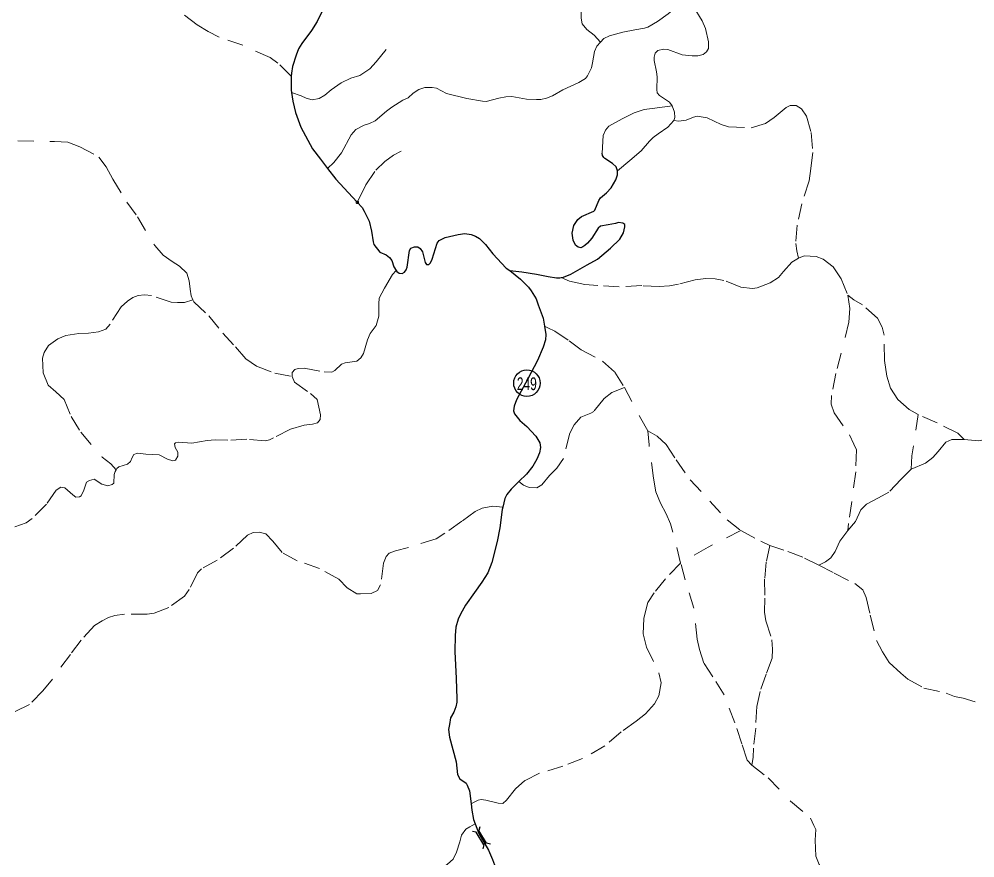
# Model space of a CAD drawing. Extents: x 703.1 to 728.9, y 7316.2 to 7344.3.
# Drawn here: x 719.66 to 725.66, y 7328.43 to 7333.69 of the extents above; entities that cross this region are included whole.
import ezdxf
from ezdxf.enums import TextEntityAlignment as Align

# ---------------------------------------------------------------- set-up
doc = ezdxf.new("R2010")
doc.units = 0
doc.header["$LTSCALE"] = 0.032
doc.header["$PDMODE"] = 32
doc.header["$PDSIZE"] = 0.016
for name, pattern in [('DOTTED', [1.5, 0.3, -1.2]), ('LONG_DASHED', [7.5, 6, -1.5]), ('MEDIUM_DASHED', [4.5, 3, -1.5])]:
    doc.linetypes.add(name, pattern=pattern)
for name, color, linetype, lineweight in [('10', 7, 'Continuous', 25), ('13', 7, 'Continuous', 25), ('4', 7, 'LONG_DASHED', 25), ('5', 7, 'LONG_DASHED', 13), ('6', 7, 'MEDIUM_DASHED', 13), ('7', 7, 'DOTTED', 13)]:
    doc.layers.add(name, color=color, linetype=linetype, lineweight=lineweight)
doc.layers.add('61', color=7, linetype='Continuous')

msp = doc.modelspace()

# ---------------------------------------------------------------- linework, layer by layer
at = {"layer": '10'}
for p, q in [((722.5521, 7328.6293), (722.5462, 7328.6051)), ((722.5942, 7328.526), (722.5462, 7328.6051)), ((722.5771, 7328.5156), (722.5711, 7328.4915)), ((722.6184, 7328.5202), (722.5942, 7328.526))]:
    msp.add_line(p, q, dxfattribs=at)
msp.add_lwpolyline([(722.5771, 7328.5156), (722.5291, 7328.5947), (722.5048, 7328.6006)], dxfattribs=at)
at = {"layer": '13'}
msp.add_circle((722.8471, 7331.4093), 0.083, dxfattribs=at)
at = {"layer": '4'}
for points in [[(721.5179, 7333.9729), (721.5617, 7333.939), (721.5822, 7333.9163), (721.5905, 7333.8858), (721.596, 7333.8481), (721.5803, 7333.7854), (721.562, 7333.7366), (721.5312, 7333.6755), (721.4968, 7333.6184), (721.435, 7333.5369), (721.414, 7333.5036), (721.3993, 7333.4648), (721.3776, 7333.3927), (721.3704, 7333.3522), (721.3692, 7333.3328)], [(721.3692, 7333.3328), (721.368, 7333.3134), (721.368, 7333.2458), (721.3702, 7333.2316)], [(721.3702, 7333.2316), (721.3788, 7333.1759), (721.3959, 7333.1054), (721.43, 7333.0134), (721.4583, 7332.9585), (721.503, 7332.8775), (721.5518, 7332.812), (721.5958, 7332.7533)], [(723.4155, 7332.7388), (723.4057, 7332.7648), (723.3825, 7332.7859), (723.3358, 7332.8165), (723.3281, 7332.8231), (723.3214, 7332.8353), (723.3186, 7332.8497)], [(721.5958, 7332.7533), (721.6496, 7332.6878), (721.7524, 7332.5753), (721.7833, 7332.5426)], [(723.0607, 7332.0703), (723.076, 7332.0733), (723.1214, 7332.0921), (723.2256, 7332.1498), (723.2897, 7332.187), (723.3706, 7332.2541), (723.4299, 7332.3118), (723.4518, 7332.3511), (723.4613, 7332.3883), (723.4602, 7332.4038), (723.4485, 7332.4121), (723.4214, 7332.416), (723.4014, 7332.4105), (723.3571, 7332.401), (723.3088, 7332.3938), (723.2939, 7332.3811), (723.2536, 7332.3179), (723.2259, 7332.2874), (723.2093, 7332.2724), (723.1982, 7332.2635), (723.1849, 7332.258), (723.1677, 7332.2607), (723.1505, 7332.2729), (723.1367, 7332.3046), (723.1306, 7332.3495), (723.1405, 7332.3961), (723.1655, 7332.4349), (723.189, 7332.4543), (723.2661, 7332.4864), (723.2722, 7332.4931), (723.2982, 7332.5546), (723.3082, 7332.5696), (723.3453, 7332.6023), (723.3756, 7332.634), (723.4049, 7332.6839), (723.4155, 7332.7138), (723.4155, 7332.7388)], [(721.7833, 7332.5426), (721.8142, 7332.5098), (721.8269, 7332.4865), (721.8574, 7332.4249), (721.872, 7332.3606), (721.8826, 7332.2957), (721.8867, 7332.2774), (721.9255, 7332.2292), (721.9643, 7332.2137), (721.9848, 7332.197), (721.9998, 7332.1771), (722.0128, 7332.1382), (722.0271, 7332.1145)], [(722.0271, 7332.1145), (722.0305, 7332.1088), (722.046, 7332.0988), (722.0638, 7332.0955), (722.0787, 7332.1038), (722.0893, 7332.1199), (722.0965, 7332.1366), (722.1098, 7332.2408), (722.1198, 7332.2558), (722.1419, 7332.2641), (722.1619, 7332.263), (722.1774, 7332.2536), (722.1913, 7332.2331), (722.2079, 7332.1643), (722.2181, 7332.1537), (722.2309, 7332.1526), (722.2425, 7332.1631), (722.2536, 7332.1853), (722.2846, 7332.2857), (722.2963, 7332.3024), (722.3348, 7332.3229), (722.4152, 7332.3401), (722.4578, 7332.3462), (722.4975, 7332.3417), (722.5241, 7332.3306), (722.549, 7332.3151), (722.5878, 7332.2774), (722.6322, 7332.2203), (722.7172, 7332.1293), (722.7403, 7332.1149)], [(722.7403, 7332.1149), (722.814, 7332.1071), (722.9077, 7332.0921), (722.9803, 7332.0772), (723.0322, 7332.0683), (723.0532, 7332.0688), (723.0607, 7332.0703)], [(722.7403, 7332.1149), (722.8058, 7332.0604), (722.8561, 7332.0114), (722.8743, 7331.987), (722.9051, 7331.9373), (722.9177, 7331.9009), (722.9478, 7331.8169), (722.9571, 7331.7654)], [(722.9571, 7331.7654), (722.9663, 7331.714), (722.9642, 7331.6811), (722.9495, 7331.6342), (722.9135, 7331.5509), (722.8533, 7331.4368), (722.7816, 7331.3045), (722.7676, 7331.2646), (722.7634, 7331.2359), (722.77, 7331.2163), (722.8029, 7331.175), (722.847, 7331.1365), (722.9029, 7331.0763), (722.927, 7331.035), (722.9312, 7331.0056), (722.9256, 7330.9734), (722.9088, 7330.9328), (722.883, 7330.888), (722.8442, 7330.8397), (722.7963, 7330.7921)], [(722.7963, 7330.7921), (722.7484, 7330.7445), (722.7215, 7330.7123), (722.7082, 7330.6871), (722.6952, 7330.6324)], [(722.6952, 7330.6324), (722.6914, 7330.6164), (722.6778, 7330.5023), (722.6607, 7330.4176), (722.6264, 7330.286), (722.6023, 7330.2195), (722.5648, 7330.1627), (722.518, 7330.0963), (722.462, 7330.0172), (722.4305, 7329.9619), (722.4155, 7329.9304), (722.4022, 7329.8807), (722.3966, 7329.8282), (722.3942, 7329.7274), (722.4036, 7329.5594), (722.4081, 7329.4313), (722.4081, 7329.411), (722.4019, 7329.3809), (722.389, 7329.3466), (722.3687, 7329.3123), (722.361, 7329.271), (722.3561, 7329.2395), (722.3617, 7329.1905), (722.4026, 7329.0358), (722.4113, 7328.956), (722.426, 7328.9301), (722.4652, 7328.9028), (722.4715, 7328.8909), (722.4869, 7328.8538), (722.4969, 7328.7732)], [(722.4969, 7328.7732), (722.5019, 7328.7327), (722.5124, 7328.6739), (722.5231, 7328.6467)], [(722.5231, 7328.6467), (722.5463, 7328.5878), (722.6058, 7328.4835), (722.6306, 7328.4233), (722.6684, 7328.3232), (722.6925, 7328.2707), (722.717, 7328.2385), (722.7471, 7328.1979), (722.8149, 7328.1412), (722.8989, 7328.0817)]]:
    msp.add_lwpolyline(points, dxfattribs=at)
at = {"layer": '5'}
for points in [[(723.8493, 7333.8296), (723.7935, 7333.7745), (723.732, 7333.7234), (723.6654, 7333.6755), (723.604, 7333.6404), (723.584, 7333.6332), (723.5226, 7333.6236), (723.4488, 7333.6076), (723.3651, 7333.5853), (723.3292, 7333.5685), (723.3076, 7333.5462)], [(723.7565, 7333.1463), (723.7401, 7333.1695), (723.6771, 7333.2118), (723.6635, 7333.2293), (723.6619, 7333.2501), (723.6635, 7333.3283), (723.6591, 7333.3602), (723.6455, 7333.4313), (723.6455, 7333.4512), (723.6503, 7333.4768), (723.6686, 7333.4928), (723.7037, 7333.5031), (723.7309, 7333.4991), (723.8202, 7333.4672), (723.8825, 7333.46), (723.9184, 7333.46), (723.9515, 7333.4688), (723.973, 7333.4855), (723.9858, 7333.5063), (723.9858, 7333.5486), (723.9674, 7333.6316), (723.9451, 7333.6803), (723.8892, 7333.7713), (723.8493, 7333.8296)], [(723.3076, 7333.5462), (723.2853, 7333.5206), (723.2701, 7333.4879), (723.2581, 7333.416), (723.2522, 7333.3849), (723.2274, 7333.3346), (723.2139, 7333.3178), (723.1732, 7333.2939), (723.0726, 7333.2468), (723.0068, 7333.2101), (722.9701, 7333.1949), (722.9334, 7333.1869), (722.9063, 7333.1869), (722.8441, 7333.1885), (722.7531, 7333.2053), (722.7151, 7333.2037), (722.6705, 7333.1949), (722.5923, 7333.175), (722.5691, 7333.1758), (722.4694, 7333.1925), (722.3437, 7333.2244), (722.2791, 7333.2572), (722.2527, 7333.262), (722.2064, 7333.262), (722.1697, 7333.2492), (722.1342, 7333.2261), (722.1015, 7333.1981), (722.0688, 7333.1822), (722.0002, 7333.1391), (721.9667, 7333.1127), (721.8944, 7333.0536), (721.8593, 7333.0353), (721.8274, 7333.0257), (721.7732, 7332.9977), (721.7448, 7332.965), (721.6842, 7332.8516), (721.6371, 7332.7925), (721.5958, 7332.7533)], [(723.3186, 7332.8497), (723.3244, 7332.9611), (723.3388, 7332.9955), (723.3611, 7333.0194), (723.4441, 7333.0665), (723.5199, 7333.1024), (723.581, 7333.124), (723.648, 7333.1327), (723.7565, 7333.1463)], [(723.7565, 7333.1463), (723.7717, 7333.1064), (723.7741, 7333.0737), (723.7677, 7333.0553)], [(723.7677, 7333.0553), (723.7302, 7333.013), (723.6704, 7332.9723), (723.6392, 7332.9483), (723.6153, 7332.9252), (723.5622, 7332.8645), (723.4912, 7332.8039), (723.4155, 7332.7388)]]:
    msp.add_lwpolyline(points, dxfattribs=at)
at = {"layer": '6'}
for points in [[(723.1938, 7333.8703), (723.1976, 7333.8236), (723.1863, 7333.7466), (723.1873, 7333.6968), (723.1938, 7333.6602), (723.222, 7333.6254), (723.268, 7333.5897), (723.3076, 7333.5462)], [(723.7677, 7333.0553), (723.7987, 7333.0509), (723.8449, 7333.0576), (723.8911, 7333.0763), (723.9146, 7333.0817), (723.9775, 7333.0717), (724.0652, 7333.0308), (724.1114, 7333.0147), (724.2534, 7333.0094), (724.3421, 7333.0371), (724.3964, 7333.074), (724.4727, 7333.1376), (724.4981, 7333.1497), (724.5353, 7333.1493), (724.5674, 7333.1292), (724.5989, 7333.083), (724.629, 7332.9798), (724.6394, 7332.8549), (724.6263, 7332.7535), (724.6173, 7332.6768), (724.5701, 7332.5337), (724.5416, 7332.3994), (724.5319, 7332.2839), (724.5389, 7332.2374), (724.5503, 7332.1932)], [(719.6553, 7332.9282), (719.8846, 7332.9227), (719.9679, 7332.9198), (720.0432, 7332.891), (720.1625, 7332.8261), (720.2081, 7332.7646), (720.2497, 7332.6873), (720.3374, 7332.5441), (720.4053, 7332.4524), (720.5133, 7332.271), (720.5654, 7332.212), (720.6218, 7332.1724), (720.6694, 7332.1426), (720.714, 7332.099), (720.7298, 7332.0504), (720.7348, 7331.9979), (720.7413, 7331.9558), (720.7531, 7331.9309)], [(724.5503, 7332.1932), (724.5845, 7332.2073), (724.6601, 7332.2019), (724.7037, 7332.1865), (724.7673, 7332.1376), (724.8179, 7332.0635), (724.8591, 7331.9604)], [(724.5503, 7332.1932), (724.5084, 7332.1667), (724.4555, 7332.1091), (724.4241, 7332.0709), (724.3712, 7332.0387), (724.2912, 7332.0056), (724.2617, 7332.0016), (724.1887, 7332.0116), (724.0823, 7332.0532), (724.0277, 7332.0629), (723.9695, 7332.0649), (723.9018, 7332.0575), (723.7967, 7332.03), (723.7415, 7332.0183), (723.6765, 7332.0143), (723.5674, 7332.0203), (723.4258, 7332.0133), (723.2919, 7332.0214), (723.2092, 7332.0284), (723.1141, 7332.0491), (723.0607, 7332.0703)], [(721.3745, 7331.4512), (721.3754, 7331.475), (721.3913, 7331.4938), (721.4121, 7331.5017), (721.4498, 7331.5027), (721.5766, 7331.4799), (721.6232, 7331.4789), (721.642, 7331.4888), (721.6846, 7331.5275), (721.7078, 7331.5369), (721.7812, 7331.5468), (721.8059, 7331.5676), (721.8228, 7331.5944), (721.8466, 7331.6816), (721.8634, 7331.7193), (721.9015, 7331.7713), (721.9183, 7331.8298), (721.9193, 7331.9062), (721.9213, 7331.9418), (721.953, 7332.0053), (722.0051, 7332.0901), (722.0271, 7332.1145)], [(720.7531, 7331.9309), (720.7591, 7331.9181), (720.8523, 7331.8309), (720.9395, 7331.7228), (721.0202, 7331.6371), (721.0846, 7331.5607), (721.151, 7331.5161)], [(724.8591, 7331.9604), (724.8706, 7331.8761), (724.8658, 7331.7917), (724.7843, 7331.4706), (724.757, 7331.332), (724.7541, 7331.2774), (724.7733, 7331.2237), (724.8686, 7331.0843), (724.8955, 7331.0268), (724.9123, 7330.9908), (724.9084, 7330.8528), (724.884, 7330.6682), (724.8624, 7330.5288), (724.8586, 7330.4866)], [(725.3004, 7331.2131), (725.2434, 7331.2443), (725.1725, 7331.3057), (725.1265, 7331.3776), (725.1044, 7331.4523), (725.0895, 7331.5525), (725.0862, 7331.7093), (725.0747, 7331.7601), (725.0459, 7331.8157), (724.9501, 7331.9), (724.8964, 7331.9317), (724.8591, 7331.9604)], [(722.9571, 7331.7654), (722.9771, 7331.7558), (723.022, 7331.7342), (723.1116, 7331.674), (723.1877, 7331.6187), (723.3215, 7331.5463), (723.3976, 7331.4787), (723.4577, 7331.3829)], [(721.151, 7331.5161), (721.2669, 7331.4715), (721.3745, 7331.4512)], [(721.3745, 7331.4512), (721.3898, 7331.4162), (721.4898, 7331.3443), (721.5326, 7331.3058), (721.5531, 7331.2116), (721.5506, 7331.1817), (721.5335, 7331.1603), (721.5018, 7331.1517), (721.4505, 7331.1449), (721.3641, 7331.1201), (721.2589, 7331.067), (721.2324, 7331.0533), (721.2067, 7331.0473), (721.0912, 7331.0576), (720.9723, 7331.0516), (720.8915, 7331.0538), (720.8411, 7331.0504), (720.7461, 7331.0324), (720.6631, 7331.0401), (720.6435, 7331.0358), (720.6375, 7331.0298), (720.6418, 7331.0059), (720.658, 7330.9759), (720.6572, 7330.952), (720.6439, 7330.9267), (720.6268, 7330.9216), (720.5934, 7330.9336), (720.5421, 7330.9592), (720.4566, 7330.9644), (720.4044, 7330.9712), (720.383, 7330.9618), (720.371, 7330.943), (720.3608, 7330.919), (720.342, 7330.901), (720.2876, 7330.8852), (720.2757, 7330.8749), (720.2706, 7330.8651)], [(723.4577, 7331.3829), (723.3786, 7331.3504), (723.3307, 7331.3135), (723.2656, 7331.2325), (723.2485, 7331.2202), (723.1859, 7331.1956), (723.1429, 7331.1489), (723.1159, 7331.0949), (723.076, 7330.9371), (723.0342, 7330.8769), (722.9876, 7330.8302), (722.9397, 7330.7713), (722.9084, 7330.7523), (722.8618, 7330.7559), (722.8262, 7330.7707), (722.7963, 7330.7921)], [(723.4577, 7331.3829), (723.5602, 7331.187), (723.6051, 7331.1102)], [(726.4168, 7331.3875), (726.342, 7331.3031), (726.2984, 7331.248), (726.2821, 7331.2126), (726.2677, 7331.1502), (726.2447, 7331.0716), (726.2203, 7331.028), (726.1867, 7331.0146), (726.1474, 7331.0089), (726.0554, 7331.0117), (725.974, 7331.0367), (725.9184, 7331.0635), (725.8513, 7331.1018), (725.8039, 7331.1148), (725.7847, 7331.1129), (725.7646, 7331.1014), (725.7263, 7331.064), (725.7071, 7331.0544), (725.6803, 7331.0467), (725.5873, 7331.0563)], [(725.3004, 7331.2131), (725.2611, 7330.9533), (725.2558, 7330.8704)], [(725.5873, 7331.0563), (725.548, 7331.0956), (725.4187, 7331.1608), (725.3004, 7331.2131)], [(723.6051, 7331.1102), (723.6627, 7331.0771), (723.7192, 7331.0255), (723.7818, 7330.9285), (723.8708, 7330.8026), (723.9936, 7330.67), (724.1022, 7330.5527), (724.1881, 7330.4852)], [(723.8107, 7330.2819), (723.7474, 7330.5281), (723.7192, 7330.5895), (723.6843, 7330.6564), (723.656, 7330.7277), (723.6413, 7330.8136), (723.6125, 7331.0218), (723.6051, 7331.1102)], [(725.5873, 7331.0563), (725.5107, 7331.0554), (725.4733, 7331.0401), (725.4245, 7330.9807), (725.3919, 7330.9433), (725.3449, 7330.9088), (725.2558, 7330.8704)], [(720.2706, 7330.8651), (720.2654, 7330.8553), (720.2586, 7330.8364), (720.256, 7330.7834), (720.2474, 7330.7731), (720.2184, 7330.7654), (720.1807, 7330.7765), (720.1337, 7330.8073), (720.1054, 7330.7988), (720.0866, 7330.7877), (720.0687, 7330.738), (720.0516, 7330.7038), (720.0409, 7330.6965), (720.0195, 7330.6956), (719.9989, 7330.7085), (719.9493, 7330.753), (719.9245, 7330.7572), (719.8963, 7330.7384), (719.8339, 7330.6503), (719.7453, 7330.56), (719.7077, 7330.5334), (719.6367, 7330.5078)], [(725.2558, 7330.8704), (725.1921, 7330.8049), (725.1154, 7330.7262), (725.0512, 7330.6898), (724.9755, 7330.6515), (724.9401, 7330.615), (724.9075, 7330.5431), (724.8586, 7330.4866)], [(722.6952, 7330.6324), (722.6752, 7330.6345), (722.6328, 7330.639), (722.5673, 7330.6248), (722.5228, 7330.6058), (722.4393, 7330.5441), (722.3331, 7330.4683), (722.2772, 7330.4332), (722.1037, 7330.38), (722.0221, 7330.3582), (721.9836, 7330.3444), (721.9637, 7330.3226), (721.9467, 7330.2808), (721.9296, 7330.1461), (721.9097, 7330.1091), (721.8699, 7330.0902), (721.803, 7330.0887), (721.7802, 7330.0887), (721.7205, 7330.1267), (721.6674, 7330.1807), (721.547, 7330.2481), (721.4071, 7330.296), (721.3123, 7330.3472), (721.2544, 7330.4183), (721.2099, 7330.4639), (721.1686, 7330.4748), (721.1307, 7330.4729), (721.0946, 7330.4567), (721.0065, 7330.3742), (720.9041, 7330.2993), (720.8059, 7330.2457), (720.7822, 7330.22), (720.7301, 7330.1166), (720.7007, 7330.074), (720.6025, 7330.0042), (720.5096, 7329.9682), (720.465, 7329.9615), (720.3237, 7329.9615), (720.2626, 7329.9525), (720.2237, 7329.9402), (720.1839, 7329.9193), (720.1365, 7329.8909), (720.0521, 7329.7979), (719.9843, 7329.7093), (719.8714, 7329.5537), (719.8122, 7329.4811), (719.7287, 7329.3948), (719.6358, 7329.3492)], [(724.1881, 7330.4852), (723.9825, 7330.3814), (723.8107, 7330.2819)], [(724.1881, 7330.4852), (724.314, 7330.4183), (724.3699, 7330.3916)], [(724.8586, 7330.4866), (724.8078, 7330.4195), (724.7795, 7330.3547), (724.7517, 7330.3145), (724.7182, 7330.2886), (724.678, 7330.2694)], [(724.3699, 7330.3916), (724.3471, 7330.2869), (724.3373, 7330.1812), (724.3379, 7330.0615), (724.3354, 7329.9743), (724.3452, 7329.919), (724.3827, 7329.8005), (724.3864, 7329.7428), (724.3839, 7329.6863), (724.3459, 7329.5856), (724.3096, 7329.4769), (724.2875, 7329.3823), (724.2814, 7329.2472), (724.2673, 7329.1213), (724.2661, 7329.0624), (724.2563, 7329.0157)], [(724.678, 7330.2694), (724.5773, 7330.3183), (724.4576, 7330.3634), (724.3699, 7330.3916)], [(723.8107, 7330.2819), (723.7155, 7330.183), (723.6443, 7330.0958), (723.6045, 7330.0338), (723.5799, 7329.9343), (723.5762, 7329.8373), (723.5959, 7329.7538), (723.6738, 7329.5935), (723.6885, 7329.5309), (723.6738, 7329.4498), (723.6474, 7329.3988), (723.5897, 7329.3374), (723.5314, 7329.2914), (723.4381, 7329.2251), (723.3362, 7329.1354), (723.1963, 7329.058), (723.0729, 7329.0095), (722.9256, 7328.9653), (722.8348, 7328.9187), (722.7746, 7328.8671), (722.7181, 7328.7958), (722.696, 7328.775), (722.6666, 7328.7762), (722.5892, 7328.7958), (722.561, 7328.8008), (722.5408, 7328.7953), (722.5169, 7328.7833), (722.4969, 7328.7732)], [(724.2563, 7329.0157), (724.2281, 7329.0476), (724.1937, 7329.1496), (724.1507, 7329.2797), (724.0832, 7329.4554), (724.0127, 7329.569), (723.9562, 7329.6537), (723.928, 7329.7397), (723.9151, 7329.8042), (723.893, 7329.9995), (723.8396, 7330.1757), (723.8107, 7330.2819)], [(724.678, 7330.2694), (724.7733, 7330.2181), (724.9031, 7330.1534), (724.953, 7330.1132), (724.974, 7330.0652), (724.9999, 7329.955), (725.0387, 7329.7964), (725.0761, 7329.7245), (725.1187, 7329.6589), (725.1916, 7329.5908), (725.2347, 7329.5544), (725.3353, 7329.4978), (725.4762, 7329.4672), (725.5284, 7329.4456), (725.5821, 7329.436), (725.6568, 7329.4111)], [(724.2563, 7329.0157), (724.3587, 7328.9363), (724.4997, 7328.7901), (724.6247, 7328.6835), (724.6463, 7328.6382), (724.6574, 7328.6122), (724.6537, 7328.5454), (724.6578, 7328.4448), (724.6786, 7328.3936), (724.7495, 7328.2796), (724.7806, 7328.2047), (724.7839, 7328.1383), (724.7787, 7328.0692), (724.7665, 7327.9716), (724.7576, 7327.8624)], [(722.5231, 7328.6467), (722.5031, 7328.6366), (722.4892, 7328.6295), (722.4647, 7328.6135), (722.4365, 7328.5767), (722.4266, 7328.5349), (722.4058, 7328.4698), (722.3855, 7328.4262), (722.3499, 7328.3943), (722.3045, 7328.3636), (722.2321, 7328.3365), (722.1167, 7328.3108), (721.9767, 7328.2592), (721.9, 7328.2095), (721.8571, 7328.153), (721.8166, 7328.0817), (721.7908, 7328.04), (721.765, 7328.0154), (721.7429, 7327.9982), (721.7234, 7327.9852)]]:
    msp.add_lwpolyline(points, dxfattribs=at)
at = {"layer": '7'}
for points in [[(721.3692, 7333.3328), (721.2855, 7333.4152), (721.2366, 7333.4489), (721.0655, 7333.5262), (720.9173, 7333.5767), (720.8479, 7333.6137), (720.7799, 7333.6553), (720.6396, 7333.7627)], [(721.3702, 7333.2316), (721.4317, 7333.2088), (721.4636, 7333.1943), (721.5008, 7333.1852), (721.5449, 7333.192), (721.5791, 7333.2133), (721.6194, 7333.2483), (721.6817, 7333.2909), (721.7433, 7333.3198), (721.7988, 7333.338), (721.8619, 7333.3799), (721.9022, 7333.4217), (721.9919, 7333.5327)], [(721.7833, 7332.5426), (721.7932, 7332.5626), (721.8378, 7332.6524), (721.9003, 7332.7445), (721.9554, 7332.798), (722.0097, 7332.8375), (722.0582, 7332.863)], [(720.7531, 7331.9309), (720.6994, 7331.9136), (720.6567, 7331.9136), (720.617, 7331.9164), (720.4929, 7331.9581), (720.4484, 7331.9619), (720.4105, 7331.9581), (720.3764, 7331.9458), (720.3424, 7331.9231), (720.3035, 7331.8871), (720.2335, 7331.7781), (720.2069, 7331.7469), (720.1615, 7331.7298), (720.099, 7331.7222), (720.0379, 7331.7198), (719.9555, 7331.7075), (719.9053, 7331.6876), (719.8476, 7331.645), (719.8201, 7331.6014), (719.8088, 7331.5654), (719.8131, 7331.474), (719.8453, 7331.3972), (719.8926, 7331.3546), (719.9461, 7331.3077), (719.9887, 7331.1997), (720.0503, 7331.1012), (720.1843, 7330.9463), (720.2373, 7330.9027), (720.2706, 7330.8651)]]:
    msp.add_lwpolyline(points, dxfattribs=at)
msp.add_point((721.7833, 7332.5426), dxfattribs=at)

# ---------------------------------------------------------------- texts
at = {"layer": '61', "width": 0.7}
msp.add_text('249', height=0.08, dxfattribs=at).set_placement((722.8463, 7331.3656), align=Align.CENTER)

doc.saveas('drawing.dxf')
